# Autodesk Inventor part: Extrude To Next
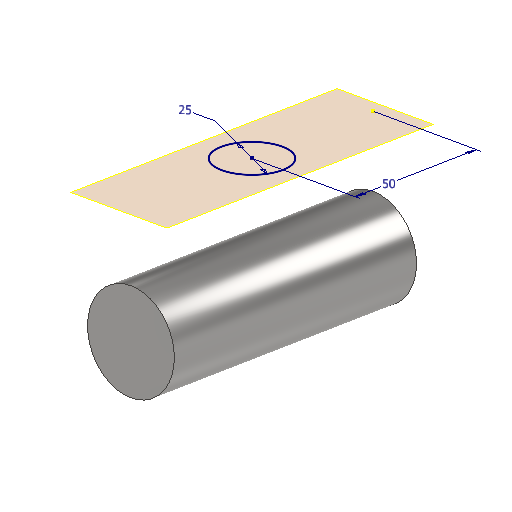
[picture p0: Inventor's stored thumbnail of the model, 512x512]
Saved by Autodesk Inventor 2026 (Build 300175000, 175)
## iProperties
Created: 2013-10
Part Number: Extrude To Next
Material: Steel, Mild
Document SubType Name: Modeling
Designer: Lars Bertram Pedersen
Density: 7.85 g/cm^3
Appearance: Semi-Polished
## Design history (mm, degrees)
sketch "Sketch1"
  geometry: C1 r 17.5 at (0, 0); 1 further point
  constraints: 1 centre point, 1 coincident
  dimensions: "d5" = 35 diameter of C1
extrude "Extrusion1" new body sketch "Sketch1" distance "d0" = 100; taper "d1" = 0 deg
workplane "Work Plane2"
  workplane "Work Plane1"
body "Solid1"
sketch "Sketch2"
  geometry: C1 r 12.5 at (0, 50); 1 further point
  constraints: 1 centre point, 1 vertical alignment
  dimensions: "d7" = 50 distance of C1.centre point (0, 0); "d8" = 25 diameter of C1
other parameters: "d2" = 25
